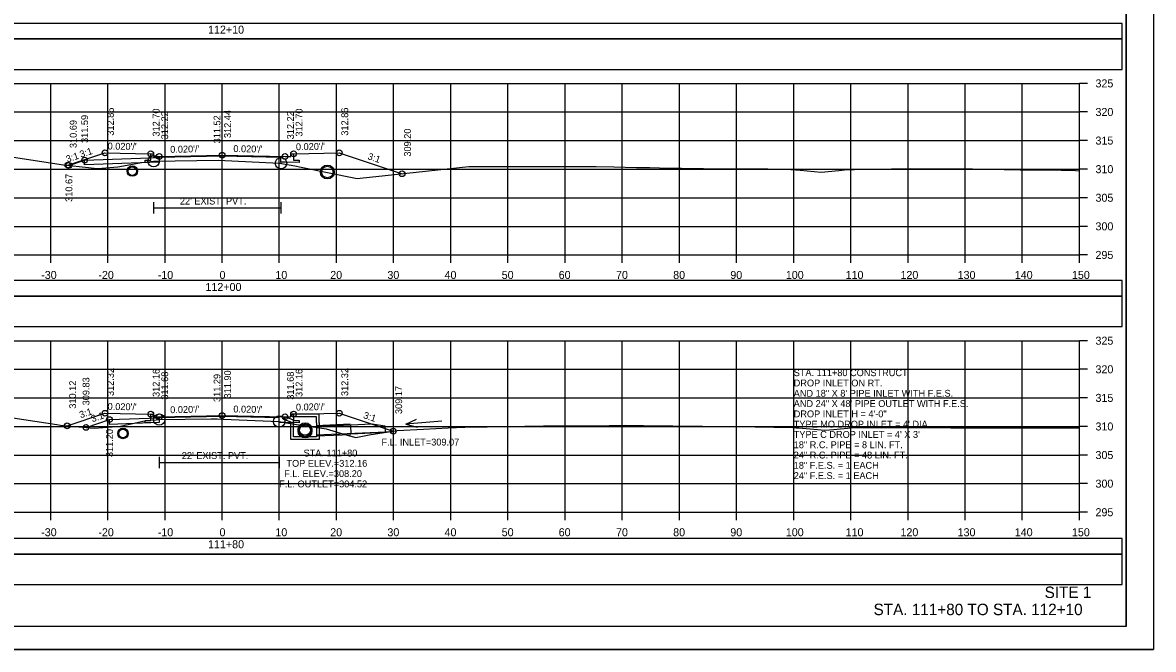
# Model space of a CAD drawing. Extents: x 1370538 to 1372872, y 376220 to 381127.
# Drawn here: x 1370673.7 to 1370871.5, y 380471.7 to 380581.3 of the extents above; entities that cross this region are included whole.
import ezdxf

# ---------------------------------------------------------------- set-up
doc = ezdxf.new("R2010")
doc.units = 0
for name, color, linetype in [('R_Border', 7, 'Continuous'), ('R_Border Notes', 7, 'Continuous'), ('R_Border PE', 7, 'Continuous'), ('R_Border Prem', 7, 'Continuous'), ('R_Dimension', 7, 'Continuous'), ('R_Fin Surface', 7, 'Continuous'), ('R_Grid', 7, 'Continuous'), ('R_Horz Alg Annot', 7, 'Continuous'), ('R_No Plot', 7, 'Continuous'), ('R_Proposed Road', 7, 'Continuous'), ('R_Water', 7, 'Continuous'), ('R_Water Annot', 7, 'Continuous'), ('R_Xsect Elev', 7, 'Continuous'), ('R_Xsect Slope', 7, 'Continuous'), ('T_Detection Zones', 7, 'Continuous')]:
    doc.layers.add(name, color=color, linetype=linetype)

msp = doc.modelspace()

# ---------------------------------------------------------------- linework, layer by layer
at = {"layer": 'R_Border'}
for p, q in [((1370696.62, 380549.93), (1370696.62, 380547.93)), ((1370696.62, 380548.93), (1370718.9, 380548.93)), ((1370718.9, 380549.93), (1370718.9, 380547.93)), ((1370697.6, 380505.42), (1370697.6, 380503.42)), ((1370718.6, 380505.42), (1370718.6, 380503.42)), ((1370697.6, 380504.42), (1370718.6, 380504.42))]:
    msp.add_line(p, q, dxfattribs=at)
for points in [[(1370708.61, 380557.98), (1370697.61, 380557.76), (1370697.61, 380556.92), (1370697.61, 380556.93), (1370695.11, 380556.88), (1370695.11, 380557.29), (1370696.11, 380557.31), (1370696.11, 380558.41)], [(1370721.11, 380558.41), (1370721.11, 380557.31), (1370722.11, 380557.29), (1370722.11, 380556.88), (1370719.61, 380556.93), (1370719.61, 380556.92), (1370718.9, 380556.94), (1370718.9, 380557.77), (1370708.61, 380557.98)], [(1370708.61, 380512.44), (1370697.61, 380512.22), (1370697.61, 380511.38), (1370697.61, 380511.39), (1370695.11, 380511.34), (1370695.11, 380511.75), (1370696.11, 380511.77), (1370696.11, 380512.87)], [(1370721.11, 380512.87), (1370721.11, 380511.77), (1370722.11, 380511.75), (1370722.11, 380511.34), (1370719.61, 380511.39), (1370719.61, 380511.38), (1370718.6, 380511.4), (1370718.6, 380512.24), (1370708.61, 380512.44)]]:
    msp.add_lwpolyline(points, dxfattribs=at)
at = {"layer": 'R_Border Notes'}
for q in [(1370866.79, 380681.17), (1370550.61, 380475.71)]:
    msp.add_line((1370866.79, 380475.71), q, dxfattribs=at)
at = {"layer": 'R_Border Prem'}
for p, q in [((1370858.61, 380540.71), (1370858.61, 380570.71)), ((1370860.01, 380570.71), (1370858.61, 380570.71)), ((1370860.01, 380565.71), (1370858.61, 380565.71)), ((1370860.01, 380560.71), (1370858.61, 380560.71)), ((1370860.01, 380555.71), (1370858.61, 380555.71)), ((1370860.01, 380550.71), (1370858.61, 380550.71)), ((1370860.01, 380545.71), (1370858.61, 380545.71)), ((1370558.61, 380540.71), (1370858.61, 380540.71)), ((1370678.61, 380539.31), (1370678.61, 380540.71)), ((1370688.61, 380539.31), (1370688.61, 380540.71)), ((1370698.61, 380539.31), (1370698.61, 380540.71)), ((1370708.61, 380539.31), (1370708.61, 380540.71)), ((1370718.61, 380539.31), (1370718.61, 380540.71)), ((1370728.61, 380539.31), (1370728.61, 380540.71)), ((1370738.61, 380539.31), (1370738.61, 380540.71)), ((1370748.61, 380539.31), (1370748.61, 380540.71)), ((1370758.61, 380539.31), (1370758.61, 380540.71)), ((1370768.61, 380539.31), (1370768.61, 380540.71)), ((1370778.61, 380539.31), (1370778.61, 380540.71)), ((1370788.61, 380539.31), (1370788.61, 380540.71)), ((1370798.61, 380539.31), (1370798.61, 380540.71)), ((1370808.61, 380539.31), (1370808.61, 380540.71)), ((1370818.61, 380539.31), (1370818.61, 380540.71)), ((1370828.61, 380539.31), (1370828.61, 380540.71)), ((1370838.61, 380539.31), (1370838.61, 380540.71)), ((1370848.61, 380539.31), (1370848.61, 380540.71)), ((1370858.61, 380539.31), (1370858.61, 380540.71)), ((1370860.01, 380540.71), (1370858.61, 380540.71)), ((1370858.61, 380495.71), (1370858.61, 380525.71)), ((1370860.01, 380525.71), (1370858.61, 380525.71)), ((1370860.01, 380520.71), (1370858.61, 380520.71)), ((1370860.01, 380515.71), (1370858.61, 380515.71)), ((1370860.01, 380510.71), (1370858.61, 380510.71)), ((1370860.01, 380505.71), (1370858.61, 380505.71)), ((1370860.01, 380500.71), (1370858.61, 380500.71)), ((1370558.61, 380495.71), (1370858.61, 380495.71)), ((1370678.61, 380494.31), (1370678.61, 380495.71)), ((1370688.61, 380494.31), (1370688.61, 380495.71)), ((1370698.61, 380494.31), (1370698.61, 380495.71)), ((1370708.61, 380494.31), (1370708.61, 380495.71)), ((1370718.61, 380494.31), (1370718.61, 380495.71)), ((1370728.61, 380494.31), (1370728.61, 380495.71)), ((1370738.61, 380494.31), (1370738.61, 380495.71)), ((1370748.61, 380494.31), (1370748.61, 380495.71)), ((1370758.61, 380494.31), (1370758.61, 380495.71)), ((1370768.61, 380494.31), (1370768.61, 380495.71)), ((1370778.61, 380494.31), (1370778.61, 380495.71)), ((1370788.61, 380494.31), (1370788.61, 380495.71)), ((1370798.61, 380494.31), (1370798.61, 380495.71)), ((1370808.61, 380494.31), (1370808.61, 380495.71)), ((1370818.61, 380494.31), (1370818.61, 380495.71)), ((1370828.61, 380494.31), (1370828.61, 380495.71)), ((1370838.61, 380494.31), (1370838.61, 380495.71)), ((1370848.61, 380494.31), (1370848.61, 380495.71)), ((1370858.61, 380494.31), (1370858.61, 380495.71)), ((1370860.01, 380495.71), (1370858.61, 380495.71))]:
    msp.add_line(p, q, dxfattribs=at)
at = {"layer": 'R_Dimension'}
for points in [[(1370672.09, 380557.82), (1370680.83, 380556.49), (1370685.23, 380555.98), (1370686.71, 380555.81), (1370686.88, 380555.82), (1370690.37, 380556.11), (1370692, 380556.4), (1370694.49, 380556.87), (1370696.59, 380557.1), (1370696.62, 380557.11), (1370696.67, 380557.11), (1370707.91, 380557.26), (1370718.65, 380556.75), (1370718.9, 380556.74), (1370719, 380556.72), (1370721.34, 380556.27), (1370722.41, 380556.08), (1370731.93, 380554.15), (1370732.3, 380554.05), (1370732.73, 380554.13), (1370738.79, 380554.76), (1370751.76, 380556.18), (1370752.43, 380556.19), (1370774.02, 380556.17), (1370777.14, 380556.09), (1370781.13, 380556.02), (1370783.43, 380555.98), (1370785.1, 380555.97), (1370792.83, 380555.85), (1370804.11, 380555.77), (1370808.11, 380555.64), (1370809.76, 380555.51), (1370813.41, 380555.2), (1370816.48, 380555.49), (1370818.05, 380555.63), (1370819.25, 380555.66), (1370829.01, 380555.83), (1370839.89, 380555.76), (1370848.26, 380555.6), (1370852.91, 380555.58), (1370857.9, 380555.45), (1370858.61, 380555.44)], [(1370671.96, 380512.22), (1370679.67, 380511.04), (1370680.32, 380510.94), (1370680.77, 380510.89), (1370686.19, 380510.42), (1370689.39, 380510.66), (1370690.53, 380510.69), (1370693.24, 380511.3), (1370695.26, 380511.73), (1370697.09, 380511.86), (1370697.6, 380511.91), (1370706.66, 380512.02), (1370707.76, 380512.03), (1370708.8, 380511.98), (1370718.6, 380511.58), (1370719.53, 380511.42), (1370721.64, 380511.08), (1370724.2, 380510.73), (1370726.81, 380510.28), (1370730.46, 380509.16), (1370731.97, 380508.78), (1370734.33, 380509.23), (1370739.21, 380509.98), (1370743.85, 380510.22), (1370748.16, 380510.49), (1370751.05, 380510.57), (1370754.95, 380510.63), (1370764.81, 380510.84), (1370776.35, 380510.87), (1370779.12, 380510.91), (1370782.3, 380510.86), (1370792.68, 380510.77), (1370798.54, 380510.69), (1370808.45, 380510.5), (1370809.02, 380510.49), (1370809.15, 380510.49), (1370809.49, 380510.46), (1370814.07, 380510.04), (1370815.62, 380510.17), (1370818.63, 380510.46), (1370822.19, 380510.54), (1370836.12, 380510.49), (1370844.67, 380510.45), (1370855.62, 380510.45), (1370858.26, 380510.47), (1370858.61, 380510.47)]]:
    msp.add_lwpolyline(points, dxfattribs=at)
at = {"layer": 'R_Fin Surface'}
for points in [[(1370681.6, 380556.4), (1370688.11, 380558.57), (1370696.11, 380558.41), (1370696.61, 380558.41), (1370696.61, 380557.91), (1370697.61, 380557.93), (1370708.61, 380558.15)], [(1370708.61, 380558.15), (1370719.61, 380557.93), (1370720.61, 380557.91), (1370720.61, 380558.41), (1370721.11, 380558.41), (1370729.11, 380558.57), (1370740.09, 380554.9)], [(1370681.5, 380510.82), (1370688.11, 380513.03), (1370696.11, 380512.87), (1370696.61, 380512.87), (1370696.61, 380512.37), (1370697.61, 380512.39), (1370708.61, 380512.61)], [(1370708.61, 380512.61), (1370719.61, 380512.39), (1370720.61, 380512.37), (1370720.61, 380512.87), (1370721.11, 380512.87), (1370729.11, 380513.03), (1370738.55, 380509.88)]]:
    msp.add_lwpolyline(points, dxfattribs=at)
at = {"layer": 'R_Grid'}
for p, q in [((1370558.61, 380570.71), (1370858.61, 380570.71)), ((1370678.61, 380540.71), (1370678.61, 380570.71)), ((1370688.61, 380540.71), (1370688.61, 380570.71)), ((1370698.61, 380540.71), (1370698.61, 380570.71)), ((1370708.61, 380540.71), (1370708.61, 380570.71)), ((1370718.61, 380540.71), (1370718.61, 380570.71)), ((1370728.61, 380540.71), (1370728.61, 380570.71)), ((1370738.61, 380540.71), (1370738.61, 380570.71)), ((1370748.61, 380540.71), (1370748.61, 380570.71)), ((1370758.61, 380540.71), (1370758.61, 380570.71)), ((1370768.61, 380540.71), (1370768.61, 380570.71)), ((1370778.61, 380540.71), (1370778.61, 380570.71)), ((1370788.61, 380540.71), (1370788.61, 380570.71)), ((1370798.61, 380540.71), (1370798.61, 380570.71)), ((1370808.61, 380540.71), (1370808.61, 380570.71)), ((1370818.61, 380540.71), (1370818.61, 380570.71)), ((1370828.61, 380540.71), (1370828.61, 380570.71)), ((1370838.61, 380540.71), (1370838.61, 380570.71)), ((1370848.61, 380540.71), (1370848.61, 380570.71)), ((1370858.61, 380540.71), (1370858.61, 380570.71)), ((1370558.61, 380565.71), (1370858.61, 380565.71)), ((1370558.61, 380560.71), (1370858.61, 380560.71)), ((1370558.61, 380555.71), (1370858.61, 380555.71)), ((1370558.61, 380550.71), (1370858.61, 380550.71)), ((1370558.61, 380545.71), (1370858.61, 380545.71)), ((1370558.61, 380540.71), (1370858.61, 380540.71)), ((1370558.61, 380525.71), (1370858.61, 380525.71)), ((1370678.61, 380495.71), (1370678.61, 380525.71)), ((1370688.61, 380495.71), (1370688.61, 380525.71)), ((1370698.61, 380495.71), (1370698.61, 380525.71)), ((1370708.61, 380495.71), (1370708.61, 380525.71)), ((1370718.61, 380495.71), (1370718.61, 380525.71)), ((1370728.61, 380495.71), (1370728.61, 380525.71)), ((1370738.61, 380495.71), (1370738.61, 380525.71)), ((1370748.61, 380495.71), (1370748.61, 380525.71)), ((1370758.61, 380495.71), (1370758.61, 380525.71)), ((1370768.61, 380495.71), (1370768.61, 380525.71)), ((1370778.61, 380495.71), (1370778.61, 380525.71)), ((1370788.61, 380495.71), (1370788.61, 380525.71)), ((1370798.61, 380495.71), (1370798.61, 380525.71)), ((1370808.61, 380495.71), (1370808.61, 380525.71)), ((1370818.61, 380495.71), (1370818.61, 380525.71)), ((1370828.61, 380495.71), (1370828.61, 380525.71)), ((1370838.61, 380495.71), (1370838.61, 380525.71)), ((1370848.61, 380495.71), (1370848.61, 380525.71)), ((1370858.61, 380495.71), (1370858.61, 380525.71)), ((1370558.61, 380520.71), (1370858.61, 380520.71)), ((1370558.61, 380515.71), (1370858.61, 380515.71)), ((1370558.61, 380510.71), (1370858.61, 380510.71)), ((1370558.61, 380505.71), (1370858.61, 380505.71)), ((1370558.61, 380500.71), (1370858.61, 380500.71)), ((1370558.61, 380495.71), (1370858.61, 380495.71))]:
    msp.add_line(p, q, dxfattribs=at)
at = {"layer": 'R_Horz Alg Annot'}
for points in [[(1370681.8, 380556.38), (1370684.55, 380557.29), (1370697.61, 380557.76)], [(1370697.61, 380557.76), (1370697.61, 380556.93), (1370684.55, 380556.46), (1370684.55, 380557.29)], [(1370684.79, 380510.54), (1370688.9, 380511.91), (1370697.61, 380512.22)], [(1370697.61, 380512.22), (1370697.61, 380511.39), (1370688.9, 380511.08), (1370688.9, 380511.91)]]:
    msp.add_lwpolyline(points, dxfattribs=at)
at = {"layer": 'R_No Plot'}
for p, q in [((1370731.03, 380511.1), (1370725.04, 380510.83)), ((1370731.11, 380509.27), (1370725.04, 380508.99)), ((1370538.21, 380471.73), (1370871.54, 380471.73))]:
    msp.add_line(p, q, dxfattribs=at)
for points in [[(1370538.2, 380685.06), (1370871.54, 380685.06), (1370871.54, 380471.72), (1370538.2, 380471.72)], [(1370784.53, 380681.17), (1370784.53, 380671.29), (1370820.26, 380671.29), (1370820.26, 380668.37), (1370843.46, 380668.37), (1370843.46, 380644.03), (1370866.79, 380644.03), (1370866.79, 380475.71), (1370550.61, 380475.71), (1370550.61, 380681.17)]]:
    msp.add_lwpolyline(points, close=True, dxfattribs=at)
for centre, radius in [((1370688.11, 380558.57), 0.5), ((1370696.11, 380558.41), 0.5), ((1370708.61, 380558.15), 0.5), ((1370708.61, 380558.15), 0.5), ((1370721.11, 380558.41), 0.5), ((1370729.11, 380558.57), 0.5), ((1370681.6, 380556.4), 0.5), ((1370681.8, 380556.38), 0.5), ((1370684.55, 380557.29), 0.5), ((1370696.62, 380557.11), 1), ((1370697.61, 380557.93), 0.5), ((1370718.9, 380556.74), 1), ((1370719.61, 380557.93), 0.5), ((1370692.89, 380555.38), 0.917), ((1370727.01, 380555.21), 1.21), ((1370740.09, 380554.9), 0.5), ((1370688.11, 380513.03), 0.5), ((1370696.11, 380512.87), 0.5), ((1370708.61, 380512.61), 0.5), ((1370708.61, 380512.61), 0.5), ((1370721.11, 380512.87), 0.5), ((1370729.11, 380513.03), 0.5), ((1370681.5, 380510.82), 0.5), ((1370688.9, 380511.91), 0.5), ((1370697.6, 380511.91), 1), ((1370697.61, 380512.39), 0.5), ((1370718.6, 380511.58), 1), ((1370719.61, 380512.39), 0.5), ((1370723.11, 380510.16), 1.21), ((1370723.11, 380509.91), 1.21), ((1370684.79, 380510.54), 0.5), ((1370691.26, 380509.48), 0.917), ((1370738.55, 380509.88), 0.5)]:
    msp.add_circle(centre, radius, dxfattribs=at)
at = {"layer": 'R_Water'}
for p, q in [((1370719.61, 380512.39), (1370721.11, 380511.87)), ((1370719.61, 380511.86), (1370720.61, 380511.51)), ((1370720.61, 380511.37), (1370720.61, 380511.51)), ((1370720.77, 380512.7), (1370720.86, 380512.87)), ((1370720.77, 380512.7), (1370721.11, 380512.37)), ((1370725.61, 380512.87), (1370720.86, 380512.87)), ((1370725.11, 380512.37), (1370721.11, 380512.37)), ((1370721.11, 380511.37), (1370721.11, 380511.87)), ((1370725.11, 380511.37), (1370725.11, 380512.37)), ((1370725.61, 380511.37), (1370725.61, 380512.87)), ((1370731.04, 380510.93), (1370725.04, 380510.66)), ((1370738.61, 380509.78), (1370725.04, 380509.16))]:
    msp.add_line(p, q, dxfattribs=at)
for points in [[(1370719.61, 380511.86), (1370719.61, 380512.39)], [(1370725.61, 380511.37), (1370725.61, 380508.41), (1370723.11, 380508.41), (1370720.61, 380508.41), (1370720.61, 380511.37)], [(1370725.11, 380511.37), (1370725.11, 380508.91), (1370723.11, 380508.91), (1370721.11, 380508.91), (1370721.11, 380511.37)]]:
    msp.add_lwpolyline(points, dxfattribs=at)
msp.add_lwpolyline([(1370731.04, 380510.93), (1370731.1, 380509.43), (1370737.18, 380509.71), (1370737.13, 380510.75), (1370734.87, 380511.11)], close=True, dxfattribs=at)
for centre, radius in [((1370692.89, 380555.38), 0.75), ((1370727.01, 380555.21), 1), ((1370723.11, 380510.16), 1), ((1370691.26, 380509.48), 0.75), ((1370723.11, 380509.91), 1)]:
    msp.add_circle(centre, radius, dxfattribs=at)
at = {"layer": 'R_Water Annot'}
for p, q in [((1370740.75, 380511.11), (1370742.61, 380511.96)), ((1370747.02, 380511.62), (1370740.75, 380511.11)), ((1370740.75, 380511.11), (1370742.73, 380510.57))]:
    msp.add_line(p, q, dxfattribs=at)
at = {"layer": 'R_Xsect Elev'}
for p, q in [((1370708.61, 380557.22), (1370708.61, 380567.22)), ((1370708.61, 380511.99), (1370708.61, 380521.99))]:
    msp.add_line(p, q, dxfattribs=at)
at = {"layer": 'T_Detection Zones'}
for points in [[(1370550.96, 380578.49), (1370866.09, 380578.49), (1370866.09, 380581.19), (1370550.96, 380581.19)], [(1370550.96, 380573.16), (1370866.09, 380573.16), (1370866.09, 380578.49), (1370550.96, 380578.49)], [(1370550.96, 380533.51), (1370866.09, 380533.51), (1370866.09, 380536.22), (1370550.96, 380536.22)], [(1370550.96, 380528.19), (1370866.09, 380528.19), (1370866.09, 380533.51), (1370550.96, 380533.51)], [(1370550.96, 380488.38), (1370866.09, 380488.38), (1370866.09, 380491.09), (1370550.96, 380491.09)], [(1370550.96, 380483.06), (1370866.09, 380483.06), (1370866.09, 380488.38), (1370550.96, 380488.38)]]:
    msp.add_lwpolyline(points, close=True, dxfattribs=at)

# ---------------------------------------------------------------- texts
at = {"layer": 'R_Border PE'}
for s, p in [('112+10', (1370706.14, 380579.41)), ('325', (1370861.41, 380570.01)), ('320', (1370861.41, 380565.01)), ('315', (1370861.41, 380560.01)), ('310', (1370861.41, 380555.01)), ('305', (1370861.41, 380550.01)), ('300', (1370861.41, 380545.01)), ('295', (1370861.41, 380540.01)), ('-30', (1370676.95, 380536.51)), ('-20', (1370686.95, 380536.51)), ('-10', (1370697.34, 380536.51)), ('0', (1370708.15, 380536.51)), ('10', (1370717.92, 380536.51)), ('20', (1370727.52, 380536.51)), ('30', (1370737.52, 380536.51)), ('40', (1370747.52, 380536.51)), ('50', (1370757.52, 380536.51)), ('60', (1370767.49, 380536.51)), ('70', (1370777.52, 380536.51)), ('80', (1370787.52, 380536.51)), ('90', (1370797.52, 380536.51)), ('100', (1370807.23, 380536.51)), ('110', (1370817.69, 380536.51)), ('120', (1370827.29, 380536.51)), ('130', (1370837.29, 380536.51)), ('140', (1370847.29, 380536.51)), ('150', (1370857.29, 380536.51)), ('112+00', (1370705.69, 380534.41)), ('325', (1370861.41, 380525.01)), ('320', (1370861.41, 380520.01)), ('315', (1370861.41, 380515.01)), ('310', (1370861.41, 380510.01)), ('305', (1370861.41, 380505.01)), ('300', (1370861.41, 380500.01)), ('295', (1370861.41, 380495.01)), ('-30', (1370676.95, 380491.51)), ('-20', (1370686.95, 380491.51)), ('-10', (1370697.34, 380491.51)), ('0', (1370708.15, 380491.51)), ('10', (1370717.92, 380491.51)), ('20', (1370727.52, 380491.51)), ('30', (1370737.52, 380491.51)), ('40', (1370747.52, 380491.51)), ('50', (1370757.52, 380491.51)), ('60', (1370767.49, 380491.51)), ('70', (1370777.52, 380491.51)), ('80', (1370787.52, 380491.51)), ('90', (1370797.52, 380491.51)), ('100', (1370807.23, 380491.51)), ('110', (1370817.69, 380491.51)), ('120', (1370827.29, 380491.51)), ('130', (1370837.29, 380491.51)), ('140', (1370847.29, 380491.51)), ('150', (1370857.29, 380491.51)), ('111+80', (1370706.14, 380489.41))]:
    msp.add_text(s, height=1.4, dxfattribs=at).set_placement(p)
at = {"layer": 'R_Proposed Road'}
for s, p in [('SITE 1', (1370852.51, 380480.71)), ('STA. 111+80 TO STA. 112+10', (1370822.58, 380477.71))]:
    msp.add_text(s, height=2, dxfattribs=at).set_placement(p)
at = {"layer": 'R_Water'}
for p in [(1370701.21, 380549.53), (1370701.55, 380505.02)]:
    msp.add_text("22' EXIST. PVT.", height=1.2, dxfattribs=at).set_placement(p)
at = {"layer": 'R_Water Annot'}
for s, p in [('STA. 111+80 CONSTRUCT', (1370808.61, 380519.51)), ('AND 18" X 8\' PIPE INLET WITH F.E.S.', (1370808.61, 380515.91)), ('DROP INLET ON RT.', (1370808.61, 380517.71)), ('AND 24" X 48\' PIPE OUTLET WITH F.E.S.', (1370808.61, 380514.11)), ('DROP INLET H = 4\'-0"', (1370808.61, 380512.31)), ("TYPE MO DROP INLET = 4' DIA.", (1370808.61, 380510.51)), ("TYPE C DROP INLET = 4' X 3'", (1370808.61, 380508.71)), ('F.L. INLET=309.07', (1370736.49, 380507.38)), ('18" R.C. PIPE = 8 LIN. FT.', (1370808.61, 380506.91)), ('STA. 111+80', (1370722.85, 380505.46)), ('24" R.C. PIPE = 48 LIN. FT. ', (1370808.61, 380505.11)), ('TOP ELEV.=312.16', (1370719.86, 380503.66)), ('18" F.E.S. = 1 EACH', (1370808.61, 380503.31)), ('F.L. OUTLET=304.52', (1370718.59, 380500.06)), ('F.L. ELEV.=308.20', (1370719.46, 380501.86)), ('24" F.E.S. = 1 EACH', (1370808.61, 380501.51))]:
    msp.add_text(s, height=1.2, dxfattribs=at).set_placement(p)
at = {"layer": 'R_Xsect Elev'}
for s, p in [('311.59', (1370685.15, 380560.29)), ('312.86', (1370689.66, 380561.57)), ('312.70', (1370697.66, 380561.41)), ('312.22', (1370699.16, 380560.93)), ('311.52', (1370708.31, 380560.22)), ('312.44', (1370710.16, 380561.15)), ('312.22', (1370721.16, 380560.93)), ('312.70', (1370722.66, 380561.41)), ('312.86', (1370730.66, 380561.57)), ('310.69', (1370683.15, 380559.4)), ('309.20', (1370741.64, 380557.9)), ('310.67', (1370682.4, 380549.99)), ('309.83', (1370685.39, 380514.4)), ('312.32', (1370689.66, 380516.03)), ('312.16', (1370697.66, 380515.87)), ('311.68', (1370699.16, 380515.39)), ('311.29', (1370708.31, 380514.99)), ('311.90', (1370710.16, 380515.61)), ('311.68', (1370721.16, 380515.39)), ('312.16', (1370722.66, 380515.87)), ('312.32', (1370730.66, 380516.03)), ('310.12', (1370683.05, 380513.82)), ('309.17', (1370740.1, 380512.88)), ('311.20', (1370689.5, 380505.35))]:
    msp.add_text(s, height=1.2, rotation=90, dxfattribs=at).set_placement(p)
at = {"layer": 'R_Xsect Slope'}
for s, rotation, p in [('3:1', 18.4332, (1370681.52, 380556.86)), ('3:1', 18.4349, (1370683.91, 380557.69)), ("0.020'/'", 358.8542, (1370688.56, 380559.16)), ("0.020'/'", 1.1458, (1370699.53, 380558.57)), ("0.020'/'", 358.8542, (1370710.56, 380558.71)), ("0.020'/'", 1.1458, (1370721.53, 380559.02)), ('3:1', 341.5651, (1370733.97, 380557.47)), ('3:1', 18.4349, (1370683.86, 380512.14)), ('3:1', 18.4332, (1370685.9, 380511.44)), ("0.020'/'", 358.8542, (1370688.56, 380513.62)), ("0.020'/'", 1.1458, (1370699.53, 380513.03)), ("0.020'/'", 358.8542, (1370710.56, 380513.17)), ("0.020'/'", 1.1458, (1370721.53, 380513.48)), ('3:1', 341.5651, (1370733.2, 380512.19))]:
    msp.add_text(s, height=1.2, rotation=rotation, dxfattribs=at).set_placement(p)

doc.saveas('drawing.dxf')
